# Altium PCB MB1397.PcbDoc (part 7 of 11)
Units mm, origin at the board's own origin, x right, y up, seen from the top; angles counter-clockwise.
Board outline 118.24 x 172.86 mm, 6 copper layers (Top Layer, L2_GND, L3_VCC, L4_SIG, L5_GND, Bottom Layer), stack 1.631 mm thick; 819 components, 632 nets, 2875 pads, 1523 vias.
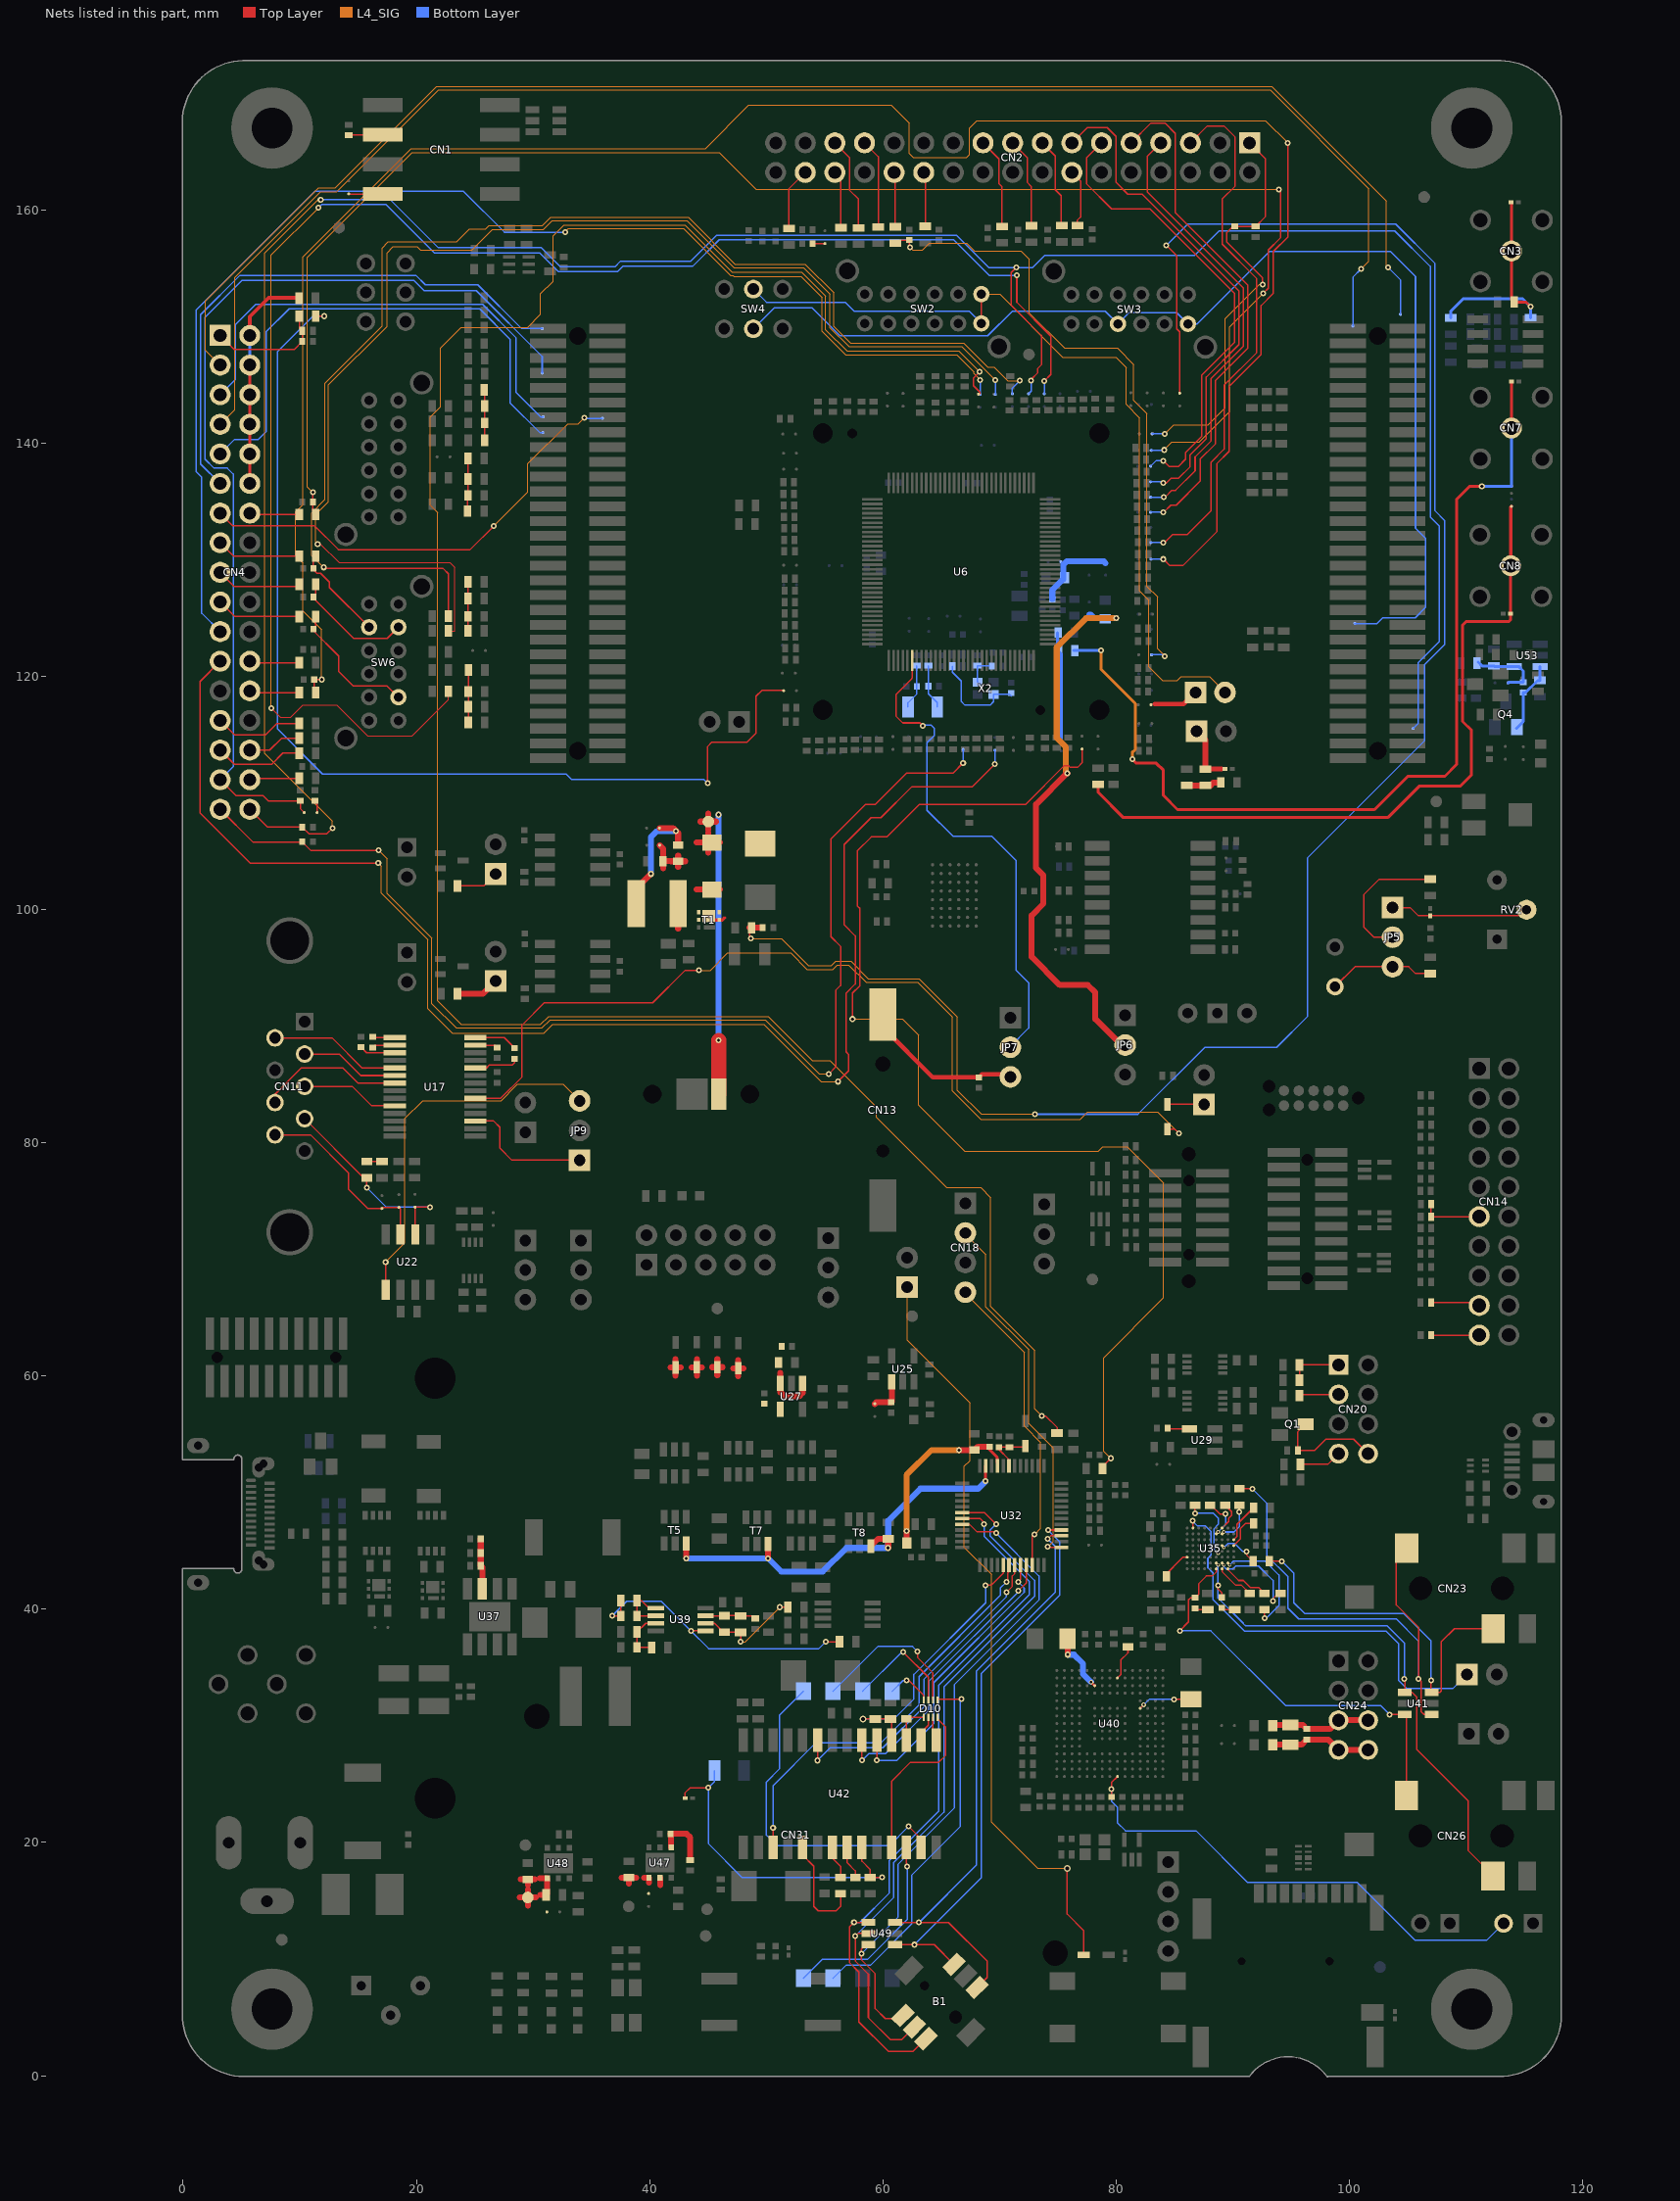
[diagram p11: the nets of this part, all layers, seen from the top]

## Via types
v1: diameter 0.508, hole 0.254, Top Layer to Bottom Layer, tented both sides, 1330 vias
v2: diameter 0.406, hole 0.203, Top Layer to Bottom Layer, tented both sides, 115 vias
v3: diameter 0.508, hole 0.254, Top Layer to Bottom Layer, 33 vias
v4: diameter 0.305, hole 0.152, Top Layer to Bottom Layer, tented both sides, 26 vias
v5: diameter 0.61, hole 0.305, Top Layer to Bottom Layer, tented both sides, 14 vias
v6: diameter 0.61, hole 0.33, Top Layer to Bottom Layer, tented both sides, 2 vias
v7: diameter 0.381, hole 0.203, Top Layer to Bottom Layer, tented both sides, 2 vias
v8: diameter 0.508, hole 0.203, Top Layer to Bottom Layer, tented both sides, 1 vias

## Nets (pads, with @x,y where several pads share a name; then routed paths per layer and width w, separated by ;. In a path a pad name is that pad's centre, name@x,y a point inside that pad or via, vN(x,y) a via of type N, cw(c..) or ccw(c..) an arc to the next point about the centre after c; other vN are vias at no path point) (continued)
MC1_PWM_1L: CN2.5 SB79.1 | length 46.5
  Top Layer w0.127: v1(84.046,131.47) 84.15,131.47 84.808,132.128 86.078,132.128 88.135,134.186 88.135,138.351 89.253,139.469 89.253,144.955 92.047,147.749 92.047,154.099 89.101,157.046 89.101,160.932 90.206,162.037 90.206,166.228 89.253,167.18 87.805,167.18 CN2.5@86.36,165.735
  Bottom Layer w0.127: SB79.1@82.967,131.47 v1(84.046,131.47)
MC1_PWM_2H: CN2.7 SB76.1 | length 38.5
  Top Layer w0.127: CN2.7@83.82,165.735 82.649,164.564 82.649,161.541 90.904,153.286 90.904,148.288 88.11,145.494 88.11,140.155 86.764,138.808 86.764,137.615 85.087,135.938 84.775,135.938 84.191,135.357 v1(84.074,135.357)
  Bottom Layer w0.127: SB76.1@82.95,135.357 SB76.1@82.95,135.357 v1(84.074,135.357)
MC1_PWM_2L: CN2.9 SB77.1 | length 44.3
  Top Layer w0.127: CN2.9@81.28,165.735 82.979,167.434 84.173,167.434 85.062,166.545 85.062,159.763 91.285,153.54 91.285,148.13 88.491,145.336 88.491,139.901 87.196,138.605 87.196,136.726 85.138,134.668 84.681,134.668 84.074,134.061 v1(84.021,134.061)
  Bottom Layer w0.127: SB77.1@82.949,134.061 v1(84.021,134.061)
MC1_PWM_3H: CN2.11 SB73.1 | length 40.3
  Top Layer w0.127: CN2.11@78.74,165.735 77.442,164.437 77.442,162.227 79.601,160.068 82.903,160.068 90.142,152.829 90.142,148.638 87.348,145.844 87.348,140.586 85.951,139.189 85.951,138.605 85.316,137.97 84.552,137.97 v1(84.046,138.478)
  Bottom Layer w0.127: SB73.1@82.949,138.016 83.414,138.478 v1(84.046,138.478)
MC1_PWM_3L: CN2.13 SB74.1 | length 43.8
  Top Layer w0.127: CN2.13@76.2,165.735 77.518,167.053 79.22,167.053 79.982,166.291 79.982,162.354 80.998,161.338 82.217,161.338 90.523,153.032 90.523,148.445 87.729,145.651 87.729,140.383 86.332,138.986 86.332,137.97 85.354,136.992 84.719,136.992 84.3,136.573 v1(84.046,136.573)
  Bottom Layer w0.127: SB74.1@82.945,136.679 83.942,136.677 v1(84.046,136.573)
MC1_STOP: C1.2 CN2.1 R9.1 SB69.1 | length 35.8
  Top Layer w0.127: CN2.1@91.44,165.735 92.809,164.363 92.809,159.428 R9.1@91.945,158.565 89.992,158.565 89.482,158.054 89.482,157.223 92.555,154.15 v1(92.555,153.591)
  L4_SIG w0.102: v1(84.173,140.787) 84.938,141.552 87.881,141.552 89.355,143.025 89.355,150.67 92.276,153.591 v1(92.555,153.591)
  Bottom Layer w0.127: SB69.1@83.078,140.788 v1(84.173,140.787)
MC1_Temp: C5.2 R7.2 SB100.1 | length 55.9
  Top Layer w0.127: R7.2@61.059,156.957 61.159,157.056 61.498,157.394 C5.2@62.27,157.395 62.271,156.817 v1(62.329,156.759)
  L4_SIG w0.102: v1(62.329,156.759) 62.55,156.538 63.396,156.538 63.98,157.122 67.183,157.122 67.843,156.461 71.854,156.461 72.565,155.75 72.565,151.127 75.562,148.13 80.109,148.13 81.506,146.733 81.506,143.634 82.624,142.517 82.624,127.709 83.538,126.794 83.538,122.347 v1(84.173,121.714)
  Bottom Layer w0.127: SB100.1@83.022,121.841 84.049,121.841 v1(84.173,121.714)
MC2_Ain: R103.2 SB60.1 | length 108.3
  Top Layer w0.102: v1(11.529,131.343) 11.76,131.343 13.36,129.743 22.875,129.743 23.298,129.32 23.298,123.879 R103.2@22.751,123.879
  L4_SIG w0.102: v1(11.529,131.343) 11.368,131.504 11.368,133.875 12.464,134.971 12.464,144.984 17.475,149.996 17.475,156.312 18.006,156.842 20.069,156.842 20.345,156.566 24.762,156.566 26.502,158.306 30.899,158.306 31.646,159.052 43.183,159.052 47.206,155.029 53.2,155.029 55.471,152.758 55.471,149.863 57.076,148.257 66.774,148.257 69.06,145.971 69.06,145.969 v1(69.642,145.39)
  Bottom Layer w0.127: SB60.1@69.642,144.178 v1(69.642,145.39)
MC2_Bin: R99.2 SB59.1 | length 109.5
  Top Layer w0.127: v1(12.037,129.334) 12.139,129.233 22.299,129.233 22.751,128.781 R99.2@22.751,125.166
  L4_SIG w0.102: v1(12.037,129.334) 11.021,130.35 11.021,134.01 12.162,135.151 12.162,145.115 17.069,150.022 17.069,156.721 17.596,157.249 23.442,157.249 24.559,158.366 25.931,158.366 26.223,158.659 30.82,158.659 31.519,159.357 43.31,159.357 47.323,155.344 53.317,155.344 55.776,152.885 55.776,149.99 57.203,148.562 66.901,148.562 68.958,146.505 69.543,146.505 70.711,145.336 v1(71.727,145.336)
  Bottom Layer w0.127: SB59.1@71.096,144.216 71.095,144.706 v1(71.727,145.336)
MC2_BusVoltage: C22.1 R77.2 SB72.1 | length 139.7
  Top Layer w0.127: v1(11.118,135.76) 11.118,134.107 R77.2@11.36,133.866 ; v1(92.606,152.829) 93.038,153.261 93.038,156.538 94.079,157.579 94.079,161.618 v1(93.952,161.745)
  L4_SIG w0.102: v1(11.118,135.76) 10.64,136.238 10.64,155.903 19.632,164.894 45.946,164.894 49.096,161.745 v1(93.952,161.745) ; v1(84.112,139.41) 84.78,140.078 87.119,140.078 89.71,142.669 89.71,149.934 v1(92.606,152.829)
  Bottom Layer w0.127: SB72.1@82.999,139.37 84.071,139.37 v1(84.112,139.41)
MC2_Cin: R119.2 SB57.1 | length 140
  Top Layer w0.102: v1(7.544,117.272) 8.331,116.484 9.205,116.484 10.271,117.551 13.162,117.551 15.829,114.884 19.634,114.884 22.751,118.001 R119.2@22.751,118.707
  Top Layer w0.127: v1(71.478,154.381) 71.478,152.062 74.394,149.146 74.394,145.872 v1(73.83,145.308)
  L4_SIG w0.102: v1(7.544,117.272) 7.544,156.108 v1(11.605,160.17)
  Bottom Layer w0.127: v1(11.605,160.17) 11.872,160.437 17.409,160.437 21.562,156.284 30.592,156.284 32.192,154.683 37.234,154.683 37.691,155.141 43.685,155.141 45.971,157.427 66.063,157.427 69.108,154.381 v1(71.478,154.381) ; SB57.1@73.831,144.216 v1(73.83,145.308)
MC2_CurrentA+: C23.2 R86.1 SW6.8 | length 8.4
  Top Layer w0.127: R86.1@11.36,130.302 11.135,130.076 11.135,129.159 11.466,128.826 11.783,128.826 12.545,128.064 12.545,127.607 SW6.8@15.951,124.202
MC2_CurrentB+: C24.2 R92.1 SW6.5 | length 10.4
  Top Layer w0.127: R92.1@11.36,127.889 11.359,126.97 11.135,126.746 11.135,126.721 14.615,123.238 17.488,123.238 SW6.5@18.451,124.202
MC2_CurrentC+: C26.2 R100.1 SW6.2 | length 11.8
  Top Layer w0.127: R100.1@11.36,125.103 11.359,124.27 11.15,124.063 11.09,124.003 11.09,123.977 13.332,121.735 13.332,120.419 14.577,119.174 17.478,119.174 SW6.2@18.451,118.202
MC2_DissipativeBrake: CN4.23 SB112.1 | length 121.9
  Top Layer w0.127: CN4.23@3.175,121.285 1.445,119.555 1.445,108.278 5.738,103.985 v1(16.736,103.985) ; v1(56.131,85.24) 57.059,86.167 57.059,87.579 56.843,87.795 56.843,92.829 57.63,93.616 57.63,97.737 56.67,98.697 56.67,105.559 58.982,107.871 59.817,107.871 62.484,110.538 67.673,110.538 v1(69.604,112.469)
  L4_SIG w0.102: v1(16.736,103.985) 16.99,103.731 16.99,101.42 20.978,97.432 20.978,91.488 23.061,89.405 30.935,89.405 31.671,90.142 49.807,90.142 54.709,85.24 v1(56.131,85.24)
  Bottom Layer w0.127: v1(69.604,112.469) SB112.1@69.604,113.657
MC2_EnA: C37.2 CN4.31 SB32.1 SB52.1 | length 84.9
  Top Layer w0.127: CN4.31@3.175,111.125 4.521,109.776 6.83,109.776 7.285,109.322 C37.2@10.044,109.323 10.043,108.651 SB32.1@10.385,108.312
  Bottom Layer w0.127: CN4.31@3.175,111.125 4.29,112.24 4.29,137.335 3.782,137.843 2.639,137.843 1.877,138.605 1.877,150.772 5.052,153.947 19.784,153.947 20.673,153.058 25.143,153.058 30.785,147.417 SB52.1@30.785,145.999
MC2_EnB: C42.2 CN4.33 SB108.1 | length 103.3
  Top Layer w0.127: CN4.33@3.175,108.585 5.969,105.791 10.218,105.791 10.93,105.077 v1(16.761,105.077) ; v1(55.344,85.9) 55.979,86.535 55.979,93.109 56.36,93.49 56.36,96.843 55.535,97.668 55.535,106.041 58.508,109.014 59.342,109.014 62.009,111.681 65.989,111.681 v1(66.878,112.57)
  L4_SIG w0.102: v1(16.761,105.077) 17.498,104.341 17.498,101.369 21.333,97.533 21.333,91.925 23.421,89.837 30.782,89.837 31.468,90.523 49.908,90.523 54.531,85.9 v1(55.344,85.9)
  Bottom Layer w0.127: v1(66.878,112.57) SB108.1@66.878,113.715
MC2_EnIndex: C39.2 CN4.34 SB58.1 SB106.1 | length 222.3
  Top Layer w0.127: CN4.34@5.715,108.585 7.239,107.058 C39.2@10.218,107.06 10.787,106.487 12.304,106.487 v1(12.799,106.982) ; v1(71.422,155.039) 70.99,154.607 70.99,151.813 73.581,149.222 73.581,146.708 73.276,146.403 73.276,146.022 72.707,145.453 v1(72.707,145.362)
  L4_SIG w0.102: v1(11.783,160.856) 11.58,160.856 7.008,156.284 7.008,113.373 12.799,107.582 v1(12.799,106.982)
  Bottom Layer w0.127: v1(11.783,160.856) 17.777,160.856 21.892,156.741 30.721,156.741 32.347,155.115 37.031,155.115 37.513,155.598 43.533,155.598 45.743,157.808 66.317,157.808 69.085,155.039 v1(71.422,155.039) 72.819,155.039 73.848,156.068 74.325,156.068 74.338,156.08 86.713,156.08 88.821,158.189 103.883,158.189 106.931,155.141 106.931,133.652 107.693,132.89 107.693,122.979 105.89,121.176 105.89,115.946 SB106.1@105.465,115.521 ; SB58.1@72.479,144.216 72.631,144.366 72.707,144.445 v1(72.707,145.362)
MC2_ICL_SHUTOUT: CN4.21 SB61.1 | length 109.8
  L4_SIG w0.102: v1(32.741,158.073) 33.043,158.375 42.89,158.375 46.911,154.353 47.14,154.353 47.216,154.277 52.982,154.277 54.785,152.474 54.785,149.578 56.792,147.571 66.317,147.571 67.79,146.098 67.79,145.946 v1(68.331,145.407)
  Bottom Layer w0.127: CN4.21@3.175,123.825 1.598,125.4 1.598,137.056 1.115,137.538 1.115,151.407 11.3,161.592 24.026,161.592 27.546,158.073 v1(32.741,158.073) ; SB61.1@68.329,144.175 68.331,144.175 v1(68.331,145.407)
MC2_PWM_1H: CN4.3 SB49.1 | length 129.1
  L4_SIG w0.102: CN4.3@3.175,146.685 1.928,147.93 1.928,152.194 11.605,161.872 13.028,161.872 21.74,170.584 93.317,170.584 103.172,160.729 103.172,155.191 v1(103.299,155.064)
  Bottom Layer w0.127: v1(103.299,155.064) 104.366,153.998 SB49.1@104.366,151.044
MC2_PWM_1L: CN4.5 SB64.1 | length 40.4
  Bottom Layer w0.127: CN4.5@3.175,144.145 4.493,145.463 4.493,150.162 6.22,151.889 25.677,151.889 28.547,149.019 28.547,144.32 30.63,142.24 SB64.1@30.871,142.24
MC2_PWM_2H: CN4.7 SB50.1 | length 132.9
  L4_SIG w0.102: CN4.7@3.175,141.605 4.417,142.847 4.417,154.175 11.796,161.554 13.167,161.554 21.892,170.279 93.19,170.279 101.671,161.798 101.671,155.595 v1(100.988,154.912)
  Bottom Layer w0.127: SB50.1@100.295,150.035 100.294,154.219 v1(100.988,154.912)
MC2_PWM_2L: CN4.9 SB68.1 | length 45.4
  Bottom Layer w0.127: CN4.9@3.175,139.065 4.417,140.307 6.449,140.307 7.109,140.967 7.109,149.527 9.091,151.508 25.423,151.508 28.039,148.892 28.039,143.431 30.579,140.891 SB68.1@30.843,140.891
MC2_PWM_3H: CN4.11 SB51.1 | length 47.8
  Bottom Layer w0.127: CN4.11@3.175,136.525 1.496,138.201 1.496,151 4.874,154.379 19.962,154.379 20.775,153.566 25.27,153.566 29.027,149.809 SB51.1@30.785,149.811
MC2_PWM_3L: CN4.13 SB66.1 | length 40.2
  Top Layer w0.127: CN4.13@3.175,133.985 4.267,132.89 11.275,132.89 13.307,130.858 24.61,130.858 v1(26.642,132.89)
  L4_SIG w0.102: v1(26.642,132.89) 29.563,135.811 29.563,138.224 32.992,141.653 33.881,141.653 v1(34.389,142.161)
  Bottom Layer w0.127: v1(34.389,142.161) 34.437,142.113 SB66.1@35.948,142.113
MC2_STOP: R21.1 SB23.1 | length 90.7
  Top Layer w0.127: R21.1@11.36,150.876 v1(12.113,150.876) ; v1(44.968,110.818) 44.968,113.98 45.339,114.351 48.362,114.351 49.121,115.11 49.121,118.285 49.629,118.793 SB23.1@51.415,118.793
  Bottom Layer w0.127: v1(12.113,150.876) 11.123,150.876 8.1,147.853 8.1,115.466 11.948,111.618 32.84,111.618 33.31,111.148 44.638,111.148 v1(44.968,110.818)
MC2_Temp: C31.2 R120.2 SB83.1 | length 178.8
  Top Layer w0.127: R120.2@11.36,118.603 11.234,118.727 C31.2@11.235,119.717 v1(11.869,119.715) ; v1(84.046,130.045) 84.602,129.487 85.722,129.487 88.618,132.382 88.618,138.224 89.685,139.291 89.685,144.849 92.428,147.592 92.428,151.788 93.469,152.829 93.469,156.411 94.714,157.655 v1(94.714,165.732)
  L4_SIG w0.102: v1(11.869,119.715) 11.869,123.99 10.259,125.6 10.259,129.715 9.624,130.35 9.624,134.08 10.259,134.715 10.259,155.953 19.548,165.242 44.773,165.242 48.486,168.958 60.703,168.958 62.253,167.409 62.253,164.818 62.608,164.462 67.155,164.462 67.434,164.742 67.434,167.002 68.069,167.637 92.809,167.637 v1(94.714,165.732)
  Bottom Layer w0.127: SB83.1@82.979,130.046 v1(84.046,130.045)
MC_DAC_OUT1: SB93.1 SW3.3 SW3.6 SW4.2 | length 99.5
  Bottom Layer w0.127: SW4.2@48.889,149.792 SW4.2@48.889,149.792 50.709,151.61 53.896,151.61 56.309,149.197 68.984,149.197 71.092,151.305 79.063,151.305 SW3.3@80.146,150.222 SW3.3@80.146,150.222 81.105,151.178 85.189,151.178 SW3.6@86.146,150.222 86.949,150.221 93.139,156.411 103.528,156.411 105.661,154.277 105.661,132.687 106.525,131.823 106.525,125.905 105.636,125.016 102.842,125.016 102.337,124.511 100.421,124.511 SB93.1@100.421,124.508
MC_DAC_OUT2: CN32.1 SB24.1 | length 3.9
  Top Layer w0.381: 83.307,117.602 85.781,117.602 CN32.1@86.792,118.613
MFX_aGPIO1: R241.1 T5.3 T7.3 T8.3 U32.11 | length 37
  Top Layer w0.254: v1(68.806,50.975) U32.11@68.807,52.292
  Top Layer w0.508: v1(43.134,44.371) T5.3@43.134,45.613 ; v1(50.15,44.359) T7.3@50.15,45.585 ; T8.3@58.951,45.409 59.578,46.035 R241.1@60.456,46.037 60.455,45.291 v1(60.424,45.26)
  Bottom Layer w0.508: v1(43.134,44.371) 43.147,44.359 v1(50.15,44.359) 51.28,43.228 54.836,43.228 56.868,45.26 v1(60.424,45.26) 60.455,45.291 60.455,47.577 63.218,50.34 68.171,50.34 v1(68.806,50.975)
MFX_IRQ_OUT: R232.1 SB26.1 | length 101.9
  Top Layer w0.127: v1(57.389,90.612) 57.389,92.836 58.011,93.459 58.011,100.097 57.81,100.298 57.81,105.031 59,106.22 60.328,106.22 63.122,109.014 72.235,109.014 75.557,112.337 75.903,112.337 76.05,112.189 76.68,112.189 77.064,112.573 SB26.1@77.064,113.759 ; R232.1@78.829,52.063 78.829,52.235 v1(79.538,52.944)
  L4_SIG w0.102: v1(57.389,90.612) 57.401,90.599 61.665,90.599 63.053,89.211 63.053,83.221 67.003,79.271 78.456,79.271 78.842,79.657 80.942,79.657 84.071,76.528 84.071,66.698 78.941,61.567 78.941,53.541 v1(79.538,52.944)
MFX_JOY_DOWN: B1.3 U32.19 U49.4 | length 62
  Top Layer w0.127: U49.4@58.749,13.142 v1(57.516,13.142) 57.122,12.748 57.122,9.7 57.935,8.887 57.935,4.616 60.471,2.08 62.581,2.08 B1.3@63.687,3.188 B1.3@63.688,3.188 ; U32.19@66.807,47.792 68.308,47.79 68.679,47.419 v1(68.679,47.292)
  Bottom Layer w0.127: v1(57.516,13.142) 58.024,13.142 60.551,15.669 60.551,18.463 64.771,22.683 64.771,33.478 72.553,41.26 72.553,42.372 68.679,46.246 v1(68.679,47.292)
MFX_JOY_LEFT: B1.1 U32.20 U49.6 | length 56.3
  Top Layer w0.127: U49.6@58.749,11.242 58.534,11.242 58.163,10.869 v1(58.163,10.462) 58.163,9.929 59.337,8.755 59.337,5.763 60.198,4.902 61.441,4.902 B1.1@61.707,5.168 ; U32.20@66.807,47.292 66.807,47.292 67.412,47.292 68.044,46.657 69.568,46.657 v1(69.695,46.53)
  Bottom Layer w0.127: v1(58.163,10.462) 61.313,13.612 61.313,18.148 66.142,22.977 66.142,33.553 73.378,40.79 73.378,42.847 v1(69.695,46.53)
MFX_JOY_RIGHT: B1.6 U32.39 U49.3 | length 51.1
  Top Layer w0.127: U49.3@61.049,13.142 v1(63.091,13.142) 65.618,13.142 68.933,9.827 68.933,8.433 B1.6@68.071,7.572 B1.6@68.071,7.572 B1.6@68.072,7.572 ; v1(74.14,46.022) 74.409,46.292 U32.39@75.307,46.292
  Bottom Layer w0.127: v1(63.091,13.142) 68.021,18.072 68.021,34.696 74.775,41.45 74.775,45.387 v1(74.14,46.022)
MFX_JOY_SEL: B1.2 U32.18 U49.5 | length 60.6
  Top Layer w0.127: U49.5@58.749,12.192 57.836,12.192 v1(57.63,11.986) 57.63,9.827 58.753,8.705 58.753,4.976 60.632,3.096 61.615,3.096 B1.2@62.697,4.178 ; U32.18@66.807,48.292 68.697,48.29 v1(69.695,47.292)
  Bottom Layer w0.127: v1(57.63,11.986) 60.932,15.288 60.932,18.306 65.227,22.601 65.227,33.325 72.997,41.095 72.997,42.466 69.187,46.276 69.187,46.784 v1(69.695,47.292)
MFX_JOY_UP: B1.4 U32.40 U49.1 | length 48
  Top Layer w0.127: U49.1@61.049,11.242 v1(62.71,11.242) 64.402,11.242 B1.4@66.09,9.551 ; B1.4@66.091,9.552 B1.4@66.091,9.553 ; v1(74.148,46.792) U32.40@75.307,46.792
  Bottom Layer w0.127: v1(62.71,11.242) 68.441,16.973 68.441,34.481 75.156,41.196 75.156,45.781 v1(74.148,46.792)
MFX_SmartCard_1V8: R275.1 R276.2 U32.29 U42.18 | length 24.2
  Top Layer w0.127: v5(58.288,30.587) R275.1@59.336,30.587 R276.2@60.657,30.587 ; R276.2@60.657,30.587 60.744,30.5 60.744,28.763 U42.18@60.743,28.765 ; v1(68.806,42.06) 68.831,42.085 69.314,42.085 70.307,43.078 U32.29@70.307,43.79
  Bottom Layer w0.127: v5(58.288,30.587) 60.94,30.587 62.649,32.296 62.649,34.404 68.806,40.561 v1(68.806,42.06)
MFX_SmartCard_3/5V: U32.30 U42.3 | length 35.9
  Top Layer w0.127: U42.3@50.583,19.585 50.584,19.583 v1(50.584,21.257) ; v1(70.584,42.339) 70.711,42.466 70.711,43.101 70.805,43.195 U32.30@70.805,43.79
  Bottom Layer w0.127: v1(50.584,21.257) 50.584,24.879 54.266,28.562 59.854,28.562 63.094,31.801 63.094,34.214 70.076,41.196 70.076,41.831 v1(70.584,42.339)
MFX_SmartCard_CMDVCC: U32.32 U42.19 | length 25
  Top Layer w0.127: v1(59.474,27.038) U42.19@59.474,28.763 ; v1(71.6,42.339) 71.806,42.545 U32.32@71.806,43.79
  Bottom Layer w0.127: v1(59.474,27.038) 61.192,27.038 64.364,30.21 64.364,33.706 72.108,41.45 72.108,41.831 v1(71.6,42.339)
MFX_SmartCard_OFF: U32.31 U42.23 | length 28.1
  Top Layer w0.127: U42.23@54.393,28.765 54.394,28.763 v1(54.394,27.033) ; v1(70.584,41.45) 71.092,41.958 71.092,42.847 71.305,43.061 U32.31@71.305,43.79
  Bottom Layer w0.127: v1(54.394,27.033) 55.476,28.118 59.997,28.118 63.536,31.656 63.536,34.021 70.584,41.069 v1(70.584,41.45)
MFX_SmartCard_RST: U32.33 U42.20 | length 25.2
  Top Layer w0.127: U42.20@58.203,28.765 58.204,28.763 v1(58.204,27.038) ; v1(71.6,41.577) 72.306,42.283 U32.33@72.306,43.79
  Bottom Layer w0.127: v1(58.204,27.038) 58.776,27.61 60.201,27.61 63.929,31.339 63.929,33.81 71.6,41.481 v1(71.6,41.577)
MFX_SWCLK: CN18.2 U32.37 | length 31.3
  Top Layer w0.127: v1(74.14,45.362) 74.211,45.291 U32.37@75.307,45.292
  L4_SIG w0.102: CN18.2@67.028,72.184 68.806,70.406 68.806,65.936 72.489,62.253 72.489,55.928 74.597,53.82 74.597,45.819 v1(74.14,45.362)
MFX_SWDIO: CN18.4 U32.34 | length 26.3
  Top Layer w0.127: U32.34@72.807,43.79 72.807,46.276 72.934,46.403 v1(72.997,46.403)
  L4_SIG w0.102: CN18.4@67.028,67.104 72.108,62.024 72.108,55.7 73.53,54.277 73.53,46.937 v1(72.997,46.403)
MFX_WAKEUP: R223.2 SB6.1 | length 198
  Top Layer w0.127: v1(68.298,146.098) 67.765,145.565 67.765,144.904 68.311,144.358 SB6.1@68.311,144.191 ; v1(73.632,56.563) 73.965,56.563 74.927,55.601 74.927,55.108 R223.2@74.929,55.109
  L4_SIG w0.102: v1(68.298,146.098) 66.518,147.876 56.919,147.876 55.09,149.705 55.09,152.601 53.033,154.658 47.038,154.658 43.019,158.677 32.634,158.677 31.709,157.752 31.709,153.845 30.655,152.791 30.655,151.026 29.538,149.908 23.848,149.908 22.07,148.13 22.07,143.101 21.181,142.212 21.181,134.668 21.816,134.033 21.816,92.179 23.853,90.142 30.655,90.142 31.341,90.828 50.162,90.828 53.947,87.043 55.446,87.043 59.433,83.055 59.433,82.184 65.471,76.147 68.374,76.147 69.238,75.283 69.238,65.961 72.997,62.202 72.997,57.198 v1(73.632,56.563)
NetC12_2: C12.2 SB2.2 | length 1.1
  Top Layer w0.127: C12.2@53.977,157.087 55.016,157.086 SB2.2@55.027,157.098
NetC16_2: C16.2 CN4.1 R21.2 R23.1 | length 10.1
  Top Layer w0.127: CN4.1@3.175,149.225 4.394,148.003 9.512,148.003 C16.2@10.218,148.709 R23.1@10.218,149.603 ; R21.2@9.96,150.876 9.959,149.863 R23.1@10.218,149.603 ; R23.1@10.218,149.606 R23.1@10.218,149.603
NetC18_1: C18.1 R31.1 R51.1 R59.2 | length 4.3
  Top Layer w0.127: R31.1@25.821,144.542 25.845,144.516 R59.2@25.846,140.228
NetC21_1: C21.1 R61.1 R66.1 R76.2 | length 4.5
  Top Layer w0.127: C21.1@24.389,135.509 24.389,134.182 R76.2@24.395,134.176 ; C21.1@24.413,135.509 R66.1@24.413,136.925 R61.1@24.413,138.674
NetC25_1: C25.1 R91.1 R95.1 R104.2 | length 4.2
  Top Layer w0.127: R104.2@24.417,123.873 24.42,123.876 R91.1@24.421,128.079
NetC32_1: C32.1 R115.2 R122.1 R125.1 | length 4.5
  Top Layer w0.127: R125.1@24.447,116.027 R115.2@24.447,120.543
NetC36_1: C36.1 R153.1 R154.1 | length 3
  Top Layer w0.127: R153.1@86.034,110.642 86.035,110.642 R153.1@86.035,110.64 ; R154.1@87.647,110.642 87.648,110.642 R154.1@87.648,110.64
  Top Layer w0.508: R153.1@86.034,110.642 86.035,110.64 R154.1@87.647,110.642 87.648,110.64 88.085,110.64 88.339,110.894 C36.1@88.962,110.894
NetC38_2: C38.2 SB32.2 | length 1.1
  Top Layer w0.127: C38.2@11.294,109.323 11.483,109.131 SB32.2@11.485,108.312
NetC41_1: C41.1 C43.2 C45.2 D1.2 LD5.1 SB34.1 TP3.1 | length 35.3
  Top Layer w0.254: LD5.1@45.916,84.149 LD5.1@45.916,84.161
  Top Layer w0.508: SB34.1@40.85,105.518 40.851,105.517 41.14,105.225 C45.2@41.142,104.151 ; 41.14,103.525 C45.2@41.142,104.151 ; 41.641,104.15 C45.2@41.142,104.151 ; 41.816,104.135 C43.2@42.44,104.135 ; 42.438,103.635 C43.2@42.44,104.135 ; 42.438,104.633 C43.2@42.44,104.135 ; 43.063,104.135 C43.2@42.44,104.135 ; 44.028,105.74 D1.2@45.027,105.74 ; 44.348,107.536 TP3.1@45.028,107.536 ; 45.027,104.861 D1.2@45.027,105.74 ; 45.027,106.619 D1.2@45.027,105.74 ; 45.027,106.858 TP3.1@45.028,107.536 ; 45.027,108.214 TP3.1@45.028,107.536 ; 45.707,107.536 TP3.1@45.028,107.536 ; v1(45.916,88.798) v1@45.926,88.788 ; D1.2@46.027,105.74 D1.2@45.027,105.74
  Top Layer w1.27: LD5.1@45.926,84.161 v1@45.926,88.788
  Bottom Layer w0.508: v1(45.916,88.798) v1(45.916,108.125)
NetC43_1: C43.1 L2.2 SB33.1 | length 11.3
  Top Layer w0.508: L2.2@38.839,100.554 38.839,101.78 v1(40.104,103.045) ; SB33.1@40.858,106.982 42.009,106.982 v1(42.263,106.728) 42.438,106.553 C43.1@42.44,105.535
  Bottom Layer w0.508: v1(40.104,103.045) 40.104,106.195 40.637,106.728 v1(42.263,106.728)
NetC49_2: C49.2 R172.2 SB10.2 | length 171.4
  Top Layer w0.127: R172.2@48.567,98.445 48.567,97.605 v1(48.664,97.508) ; v1(84.3,156.944) 85.189,156.055 85.189,149.781 85.443,149.527 SB10.2@85.443,144.272
  Top Layer w0.508: R172.2@48.567,98.445 C49.2@49.451,98.445
  L4_SIG w0.102: v1(48.664,97.508) 51.28,97.508 53.617,95.171 55.598,95.171 55.979,95.552 57.249,95.552 58.748,94.054 63.116,94.054 66.396,90.775 66.396,84.501 68.45,82.446 v1(73.02,82.446)
  Bottom Layer w0.127: v1(73.02,82.446) 81.862,82.446 87.602,88.186 93.749,88.186 96.416,90.853 96.416,104.442 106.423,114.45 106.423,120.978 108.151,122.705 108.151,133.373 107.338,134.186 107.338,155.395 103.96,158.773 86.129,158.773 v1(84.3,156.944)
NetC54_2: C54.2 U17.3 | length 3.1
  Top Layer w0.127: C54.2@15.24,88.195 15.723,87.711 U17.3@18.14,87.713
NetC55_1: C55.1 U17.1 | length 1.9
  Top Layer w0.127: C55.1@16.256,89.07 16.312,89.012 U17.1@18.14,89.013
NetC55_2: C55.2 U17.2 | length 2
  Top Layer w0.127: C55.2@16.256,88.17 16.449,88.362 U17.2@18.14,88.363
NetC56_2: C56.2 U17.27 | length 2
  Top Layer w0.127: U17.27@25.04,88.363 26.723,88.362 C56.2@26.924,88.163
NetC57_1: C57.1 U17.24 | length 3.9
  Top Layer w0.127: U17.24@25.04,86.413 26.01,86.411 26.261,86.662 28.219,86.662 28.42,86.863 C57.1@28.42,87.229
NetC57_2: C57.2 U17.28 | length 3.7
  Top Layer w0.127: U17.28@25.04,89.013 27.536,89.012 C57.2@28.42,88.128
NetC59_2: C59.2 CN13.1 JP7.3 | length 14.1
  Top Layer w0.381: CN13.1@59.992,91.004 59.992,89.888 64.282,85.598 C59.2@68.227,85.598 68.481,85.852 70.708,85.852 JP7.3@70.924,85.647 JP7.3@70.924,85.725
NetC60_1: C60.1 CN11.4 SB37.1 U22.6 | length 18
  Top Layer w0.127: CN11.4@10.414,82.063 15.486,76.987 C60.1@15.748,76.989 v1(15.748,76.149) ; U22.6@19.905,72.14 19.881,72.166 SB37.1@19.88,74.477 v1(21.176,74.475) ; U22.6@19.906,72.139 U22.6@19.907,72.141
  Bottom Layer w0.127: v1(15.748,76.149) 17.419,74.475 v1(21.176,74.475)
NetC60_2: C60.2 R192.1 | length 1.3
  Top Layer w0.127: C60.2@15.748,78.389 C60.2@15.748,78.389 R192.1@17.044,78.387
NetC63_2: C63.2 C66.1 D3.2 D4.2 D5.2 D6.2 U27.1 U27.3 | length 13.9
  Top Layer w0.508: 41.77,60.736 D5.2@42.219,60.738 ; 42.217,60.028 D5.2@42.219,60.738 ; 42.217,61.445 D5.2@42.219,60.738 ; 42.667,60.736 D5.2@42.219,60.738 ; 43.591,60.744 D4.2@44.041,60.745 ; 44.041,60.035 D4.2@44.041,60.745 ; 44.041,61.453 D4.2@44.041,60.745 ; 44.488,60.744 D4.2@44.041,60.745 ; 45.352,60.754 D3.2@45.799,60.754 ; 45.799,60.046 D3.2@45.799,60.754 ; 45.799,61.46 D3.2@45.799,60.754 ; 46.248,60.754 D3.2@45.799,60.754 ; 47.145,60.668 D6.2@47.594,60.67 ; 47.595,59.962 D6.2@47.594,60.67 ; 47.595,61.377 D6.2@47.594,60.67 ; 48.042,60.668 D6.2@47.594,60.67 ; 51.204,60.287 U27.3@51.204,59.352 51.204,58.604 51.556,58.252 52.802,58.252 53.104,58.554 U27.1@53.104,59.352
NetC71_2: C71.2 U27.4
NetC72_2: C72.2 SB41.1 U25.1 | length 3.2
  Top Layer w0.508: SB41.1@59.306,57.607 59.447,57.747 C72.2@60.706,57.747 60.753,57.794 U25.1@60.753,59.506
NetC74_2: C74.2 U29.4 | length 1.9
  Top Layer w0.127: C74.2@84.404,55.527 84.473,55.458 U29.4@86.264,55.459
NetC76_2: C76.2 C77.2 L3.2 U32.9 | length 15.5
  Top Layer w0.254: C77.2@69.145,53.945 69.144,53.685 69.807,53.023 U32.9@69.807,52.596
  Top Layer w0.508: L3.2@62.017,45.715 v1(62.017,46.716) ; v1(66.52,53.652) C76.2@67.861,53.653 68.153,53.945 C77.2@69.145,53.945
  L4_SIG w0.508: v1(62.017,46.716) 62.017,51.501 64.168,53.652 v1(66.52,53.652)
NetC78_2: C78.2 D7.1 R225.1 U32.7 | length 4.3
  Top Layer w0.127: U32.7@70.807,52.292 70.805,52.837 69.944,53.698 C78.2@69.945,53.903 72.111,53.901 D7.1@72.207,53.997
NetC85_1: C85.1 U35.E6 | length 6.4
  Top Layer w0.127: v1(86.761,48.23) C85.1@86.763,48.926 ; U35.E6@88.577,44.966 88.577,44.966 v4(88.735,44.806)
  Bottom Layer w0.127: v1(86.761,48.23) 88.341,48.23 88.745,47.826 88.745,47.267 88.364,46.886 88.364,45.176 v4(88.735,44.806)
NetC86_2: C86.2 U35.A7 | length 2.5
  Top Layer w0.127: U35.A7@89.077,46.966 89.634,47.523 89.634,47.8 89.888,48.054 89.888,48.374 89.339,48.925 C86.2@89.339,48.926
NetC87_1: C87.1 U35.B7 | length 3.6
  Top Layer w0.127: U35.B7@89.077,46.466 v4(89.235,46.624) ; v1(90.551,48.336) C87.1@90.552,48.926
  Bottom Layer w0.127: v4(89.235,46.624) 90.109,46.624 90.551,47.066 v1(90.551,48.336)
NetC87_2: C87.2 CN23.6 U41.4 | length 44.5
  Top Layer w0.127: C87.2@90.552,50.326 v1(91.676,50.325) ; CN23.6@104.91,45.233 104.013,44.336 104.013,40.361 105.918,38.456 v1(105.918,34.036) 106.147,33.807 106.147,31.217 106.388,30.975 U41.4@107.04,30.975
  Bottom Layer w0.127: v1(91.676,50.325) 92.936,49.065 92.936,44.574 94.714,42.796 94.714,40.095 95.645,39.164 104.022,39.164 105.918,37.269 v1(105.918,34.036)
NetC88_2: C88.2 U35.B6 | length 3.7
  Top Layer w0.127: C88.2@88.04,48.901 88.153,48.9 88.897,48.156 89.355,48.156 v1(89.38,48.181) ; U35.B6@88.577,46.466 88.577,46.464 v4(88.735,46.624)
  Bottom Layer w0.127: v4(88.735,46.624) 89.38,47.269 v1(89.38,48.181)
NetC90_2: C90.2 U35.C9 | length 3.5
  Top Layer w0.127: U35.C9@90.077,45.966 90.362,46.25 90.362,47.084 90.352,47.093 90.352,47.266 C90.2@91.787,48.701
NetC91_2: C91.2 U35.D9 | length 3
  Top Layer w0.127: U35.D9@90.077,45.466 90.65,46.038 90.65,46.911 91.11,47.371 C91.2@91.787,47.373
NetC95_1: C95.1 R247.1 R251.2 U37.3 | length 4.4
  Top Layer w0.508: C95.1@25.514,46.038 R247.1@25.514,44.815 R251.2@25.514,43.728 25.654,43.588 U37.3@25.654,41.745
NetC99_1: C99.1 U35.D7 | length 3.7
  Top Layer w0.127: U35.D7@89.077,45.466 v4(89.235,45.306) ; v1(91.183,44.955) 91.183,44.661 C99.1@91.727,44.117
  Bottom Layer w0.127: v4(89.235,45.306) 89.573,45.641 90.167,45.641 90.853,44.955 v1(91.183,44.955)
NetC99_2: C99.2 CN23.4 U41.6 | length 32.9
  Top Layer w0.127: C99.2@93.127,44.117 C99.2@93.133,44.117 v1(94.206,44.117) ; v1(106.991,33.902) 106.991,33.066 106.799,32.875 U41.6@107.04,32.875 107.757,32.875 107.874,32.992 107.874,37.211 108.994,38.331 CN23.4@112.31,38.333
  Bottom Layer w0.127: v1(94.206,44.117) 95.222,43.101 95.222,40.564 96.162,39.624 104.678,39.624 106.991,37.312 v1(106.991,33.902)
NetC101_2: C101.2 U35.F1 | length 2.6
  Top Layer w0.127: C101.2@84.297,42.822 84.468,42.994 84.468,43.209 85.315,44.055 85.725,44.465 U35.F1@86.077,44.466
NetC103_1: C103.1 U35.G8 | length 10.1
  Top Layer w0.127: U35.G8@89.577,43.966 v4(89.736,43.805) ; C103.1@92.71,39.965 92.71,39.263 v1(92.746,39.228)
  Bottom Layer w0.127: v4(89.736,43.805) 90.048,44.117 92.774,44.117 93.952,42.939 93.952,40.307 92.873,39.228 v1(92.746,39.228)
NetC103_2: C103.2 U35.H8 | length 4
  Top Layer w0.127: U35.H8@89.577,43.466 89.576,43.388 90.498,42.466 90.904,42.466 91.495,41.876 92.2,41.876 C103.2@92.71,41.365
NetC104_2: C104.2 U35.G7 | length 8.1
  Top Layer w0.127: U35.G7@89.077,43.966 v4(89.235,43.805) ; v1(93.444,40.688) 93.444,40.917 93.893,41.365 C104.2@94.107,41.365
  Bottom Layer w0.127: v4(89.235,43.805) 89.235,43.652 89.431,43.457 89.99,43.457 90.244,43.711 92.199,43.711 93.444,42.466 v1(93.444,40.688)
NetC105_2: C105.2 U35.H7 | length 3.4
  Top Layer w0.127: U35.H7@89.077,43.466 89.078,43.464 89.078,43.226 90.218,42.085 90.719,42.085 C105.2@91.448,41.356
NetC106_1: C106.1 CN26.4 U35.G6 U41.1 | length 45.3
  Top Layer w0.127: U35.G6@88.577,43.966 88.577,43.965 v4(88.735,43.805) ; v1(88.735,42.06) 88.735,41.73 89.047,41.417 C106.1@89.047,41.015 C106.1@89.047,41.006 ; v1(104.699,34.011) 104.74,33.969 U41.1@104.74,32.875 105.368,32.875 105.756,32.487 105.756,28 110.16,23.597 110.16,19.329 112.291,17.199 CN26.4@112.291,17.124
  Bottom Layer w0.127: v4(88.735,43.805) v1(88.735,42.06) 88.735,40.952 90.895,38.792 ; 90.885,38.782 91.085,38.583 103.223,38.583 104.699,37.107 v1(104.699,34.011)
NetC106_2: C106.2 R255.2 | length 1.2
  Top Layer w0.127: C106.2@89.047,40.104 89.197,39.954 R255.2@90.152,39.956
NetC107_1: C107.1 CN26.6 U35.H6 U41.3 | length 36.4
  Top Layer w0.127: v1(85.443,38.148) 86.205,38.91 86.205,40.815 86.375,40.985 86.761,40.985 86.763,40.987 87.094,41.316 87.094,42.212 87.729,42.847 88.242,42.847 88.577,43.182 U35.H6@88.577,43.466 ; v1(103.454,30.963) 103.467,30.975 U41.3@104.74,30.975 104.889,30.826 CN26.6@104.891,24.024
  Bottom Layer w0.127: v1(85.443,38.148) 88.11,38.148 94.508,31.75 102.667,31.75 v1(103.454,30.963)
NetC107_2: C107.2 R256.2 | length 1.1
  Top Layer w0.127: C107.2@86.761,40.084 86.891,39.954 R256.2@87.84,39.956
NetC110_1: C110.1 R260.1 R270.2 U39.5 | length 25.3
  Top Layer w0.127: v1(36.774,39.424) C110.1@37.519,39.425 R260.1@37.519,40.741 ; v1(43.533,38.148) 44.77,38.148 U39.5@44.78,38.14 ; v1(55.09,37.208) 56.276,37.208 R270.2@56.277,37.208
  Bottom Layer w0.127: v1(36.774,39.424) 38.033,40.683 40.998,40.683 v1(43.533,38.148) 45.057,36.624 54.506,36.624 v1(55.09,37.208)
NetC110_2: C110.2 R260.2 U39.1 U39.2 | length 4.8
  Top Layer w0.127: U39.2@40.53,39.441 40.516,39.425 C110.2@38.919,39.425 R260.2@38.919,40.741 39.29,40.741 39.941,40.089 U39.1@40.531,40.089
NetC111_1: C111.1 R262.2 R265.1 U39.6 | length 9.4
  Top Layer w0.127: U39.6@44.78,38.79 45.56,38.788 46.307,38.042 47.77,38.042 R265.1@47.802,38.012 v1(47.8,37.208) ; v1(51.153,40.178) R262.2@51.839,40.179
  L4_SIG w0.102: v1(47.8,37.208) 48.186,37.208 v1(51.153,40.178)
NetC111_2: C111.2 R265.2 R266.1 U39.7 | length 4.4
  Top Layer w0.127: U39.7@44.78,39.441 46.401,39.439 46.403,39.444 47.77,39.444 R265.2@47.802,39.412 48.854,39.411 R266.1@49.054,39.214
NetC114_2: C114.2 U40.J14 | length 3
  Top Layer w0.127: U40.J14@80.105,34.103 80.409,34.404 80.409,35.654 81.011,36.256 C114.2@81.011,36.772
NetC115_2: C115.2 U40.F13 | length 5.7
  Top Layer w0.254: v2(77.851,33.755) 78.034,33.572 ; v2(77.851,33.755) 78.034,33.572 ; U40.F13@78.155,33.453 78.034,33.572 ; U40.F13@78.155,33.453 78.034,33.572
  Top Layer w0.508: v1(75.832,36.106) C115.2@75.833,37.472
  Bottom Layer w0.508: v1(75.832,36.106) 76.385,36.106 77.163,35.329 77.163,34.442 v2@77.851,33.757
NetC120_2: C120.2 R268.1 R271.2 U39.3 | length 4.5
  Top Layer w0.127: R271.2@40.169,36.722 R271.2@40.169,36.722 C120.2@38.919,36.723 R268.1@38.919,38.051 39.658,38.79 U39.3@40.53,38.79
NetC122_2: C122.2 U40.M10 | length 4.7
  Top Layer w0.127: U40.M10@82.055,31.504 v2(82.357,31.806) ; v1(84.968,32.273) C122.2@86.402,32.275
  Bottom Layer w0.127: v2@82.359,31.806 82.827,32.273 v1(84.968,32.273)
NetC126_1: C126.1 D10.1 U42.17 | length 3.4
  Top Layer w0.127: U42.17@62.013,28.765 62.014,28.763 C126.1@62.014,30.587 ; C126.1@62.013,30.588 C126.1@62.014,30.587 ; D10.1@63.494,30.733 62.159,30.731 C126.1@62.014,30.587
NetC129_1: C129.1 C132.2 CN24.5 CN24.6 L6.2 | length 8.6
  Top Layer w0.508: L6.2@93.434,30.023 93.495,30.084 95.992,30.084 C132.2@96.342,29.736 ; C132.2@96.342,29.736 98.316,29.736 CN24.5@99.06,30.48 CN24.6@101.6,30.48
NetC129_2: C129.2 C132.1 CN24.7 CN24.8 L7.2 | length 8.7
  Top Layer w0.508: L7.2@93.434,28.385 95.89,28.385 C132.1@96.342,28.836 ; C132.1@96.342,28.836 98.164,28.836 CN24.7@99.06,27.94 CN24.8@101.6,27.94
NetC141_2: C141.2 CN30.2 U40.J1 | length 42.9
  Top Layer w0.127: C141.2@79.591,23.899 v1(79.591,24.559) 79.591,25.138 U40.J1@80.105,25.653
  Bottom Layer w0.127: v1(79.591,24.559) 79.591,23.556 80.094,23.05 80.094,21.704 80.795,21.003 86.84,21.003 91.285,16.558 100.683,16.558 105.636,11.605 111.755,11.605 CN30.2@113.215,13.066
NetC146_1: C146.1 R289.1 U47.1 | length 5
  Top Layer w0.508: U47.1@41.842,19.577 41.841,20.673 C146.1@41.773,20.742 43.16,20.742 43.472,20.429 R289.1@43.472,18.502
NetC149_2: C149.2 SB47.1 U47.4 U47.5 | length 3.2
  Top Layer w0.508: 37.589,16.993 C149.2@38.215,16.994 ; 38.214,16.495 C149.2@38.215,16.994 ; 38.837,16.993 C149.2@38.215,16.994 ; 39.538,16.975 U47.4@39.942,16.977 39.941,16.548 ; 40.891,16.33 U47.5@40.892,16.977
NetC151_2: C151.2 R292.2 SB48.1 TP8.1 U48.4 | length 7
  Top Layer w0.508: 28.872,15.283 TP8.1@29.55,15.284 ; 28.926,16.84 C151.2@29.55,16.84 ; 29.55,14.605 TP8.1@29.55,15.284 ; 29.55,15.961 TP8.1@29.55,15.284 ; 29.55,16.34 C151.2@29.55,16.84 ; 30.173,16.84 C151.2@29.55,16.84 ; 30.229,15.283 TP8.1@29.55,15.284 ; 30.579,16.939 30.597,16.921 U48.4@31.115,16.921 ; 30.617,15.499 R292.2@31.116,15.5 31.216,15.6 U48.4@31.216,16.924
NetC154_1: C154.1 U42.5 | length 9.1
  Top Layer w0.127: U42.5@53.123,19.585 53.124,19.583 53.124,18.905 54.074,17.955 54.074,14.526 54.455,14.145 55.979,14.145 56.36,14.526 C154.1@56.36,15.604
NetC154_2: C154.2 U42.7 | length 2.9
  Top Layer w0.127: U42.7@55.663,19.585 55.664,19.583 55.664,18.651 56.36,17.955 C154.2@56.36,17.005
NetC155_1: C155.1 U42.8 | length 2.9
  Top Layer w0.127: U42.8@56.933,19.585 56.934,19.583 56.934,18.27 57.63,17.574 C155.1@57.63,17.005
NetC169_2: C169.2 L8.1 SB84.2 SB85.2 SB86.1 | length 7.2
  Bottom Layer w0.508: C169.2@74.521,126.609 74.521,127.389 75.454,128.324 75.454,129.558 75.482,129.586 75.743,129.842 78.93,129.842 79.096,129.68 SB84.2@79.093,129.68
NetC171_2: C171.2 R310.2 SB116.2 | length 9.2
  Bottom Layer w0.254: C171.2@74.966,123.746 74.966,122.225 74.963,122.222 75.018,122.167 75.283,121.905 SB116.2@75.283,114.696
NetC177_2: C177.2 R313.1 X2.3 | length 2.4
  Bottom Layer w0.127: X2.3@68.134,119.499 68.133,119.499 68.102,119.53 68.102,120.896 69.073,120.896 C177.2@69.103,120.866
NetC178_2: C178.2 R317.1 X2.1 | length 8.6
  Bottom Layer w0.127: R317.1@65.953,120.866 R317.1@65.953,120.866 ; R317.1@65.954,120.866 65.954,120.338 66.703,119.588 66.703,117.849 67.028,117.523 69.187,117.523 69.482,117.818 69.482,118.448 70.858,118.448 70.878,118.428 C178.2@71.002,118.299
NetC181_1: C181.1 R311.2 R316.1 SB102.2 U53.4 | length 6.5
  Bottom Layer w0.254: R316.1@111.036,121.206 111.354,120.889 112.367,120.889 112.413,120.841 U53.4@114.14,120.841 ; SB102.2@113.604,119.428 113.67,119.497 C181.1@114.907,119.497 114.907,120.444 114.511,120.841 U53.4@114.14,120.841 ; U53.4@114.141,120.843 U53.4@114.14,120.841
NetC181_2: C181.2 Q4.1 R318.1 U53.3 | length 6.4
  Bottom Layer w0.254: Q4.1@114.333,115.534 114.336,115.534 114.907,116.106 C181.2@114.907,118.597 115.09,118.595 116.114,119.619 116.304,119.619 116.336,119.653 116.34,119.657 U53.3@116.341,120.843
NetC182_2: C182.2 R314.1 X3.1 | length 3.8
  Bottom Layer w0.127: R314.1@63.906,120.896 63.906,120.625 63.901,120.62 63.901,118.491 64.651,117.742 X3.1@64.651,117.376
NetC183_2: C183.2 R315.1 X3.2 | length 3.8
  Bottom Layer w0.127: X3.2@62.149,117.376 62.149,117.724 62.903,118.478 R315.1@62.903,120.896
NetCN1_4: CN1.4 R1.1 | length 3
  Top Layer w0.127: R1.1@14.192,166.377 14.244,166.428 CN1.4@17.135,166.429
NetCN1_8: CN1.8 SB1.1 | length 3
  Top Layer w0.127: SB1.1@14.192,161.372 14.214,161.348 CN1.8@17.135,161.349
NetCN2_14: CN2.14 R3.1 | length 5
  Top Layer w0.127: CN2.14@76.2,163.195 76.97,162.423 76.97,159.408 76.683,159.118 76.683,158.608 R3.1@76.68,158.608
NetCN2_15: CN2.15 R2.2 | length 7.8
  Top Layer w0.127: CN2.15@73.66,165.735 74.775,164.617 74.775,161.719 75.283,161.211 R2.2@75.283,158.608
NetCN2_17: CN2.17 R4.2 | length 7.8
  Top Layer w0.127: CN2.17@71.12,165.735 72.362,164.49 72.362,162.354 72.725,161.991 R4.2@72.726,158.624
NetCN2_19: CN2.19 R6.2 | length 7.8
  Top Layer w0.127: CN2.19@68.58,165.735 69.949,164.363 69.949,162.227 70.203,161.973 R6.2@70.203,158.608
NetCN2_24: CN2.24 R5.1 | length 4.7
  Top Layer w0.127: CN2.24@63.5,163.195 63.635,163.06 R5.1@63.635,158.587
NetCN2_26: CN2.26 R7.1 | length 4.9
  Top Layer w0.127: CN2.26@60.96,163.195 61.059,163.093 R7.1@61.059,158.356
NetCN2_27: CN2.27 R8.2 | length 7.9
  Top Layer w0.127: CN2.27@58.42,165.735 59.604,164.551 59.604,158.422 R8.2@59.535,158.354
NetCN2_29: CN2.29 R11.2 | length 8.2
  Top Layer w0.127: CN2.29@55.88,165.735 57.122,164.49 57.122,161.694 57.884,160.932 R11.2@57.884,158.354
NetCN2_30: CN2.30 R10.1 | length 5
  Top Layer w0.127: CN2.30@55.88,163.195 56.36,162.715 R10.1@56.36,158.354
NetCN2_32: CN2.32 R12.1 | length 5.4
  Top Layer w0.127: R12.1@51.915,158.356 51.915,161.768 CN2.32@53.34,163.195
NetCN3_1: CN3.1 R19.2 R302.1 R303.2 U2.1 | length 19.4
  Top Layer w0.254: U2.1@113.861,160.655 113.883,160.63 113.883,152.265 R19.2@114.084,152.068 ; R19.2@114.084,152.067 115.161,152.067 v1(115.542,151.684)
  Bottom Layer w0.254: R303.2@108.684,150.736 108.684,151.305 109.753,152.375 114.851,152.375 v1(115.542,151.684) R302.1@115.542,150.738 R302.1@115.542,150.734
NetCN4_2: CN4.2 CN4.4 CN4.6 CN4.8 CN4.10 CN4.12 R18.1 | length 19.2
  Top Layer w0.254: CN4.12@5.715,136.525 CN4.10@5.715,139.065 CN4.8@5.715,141.605 CN4.6@5.715,144.145 CN4.4@5.715,146.685
  Top Layer w0.305: CN4.2@5.715,149.225 5.715,150.825 7.338,152.448 R18.1@9.939,152.448
  Bottom Layer w0.254: CN4.4@5.715,146.685 CN4.2@5.715,149.225
NetCN4_14: CN4.14 R77.1 | length 4.3
  Top Layer w0.127: CN4.14@5.715,133.985 5.834,133.866 R77.1@9.96,133.866
NetCN4_15: CN4.15 R86.2 | length 7.3
  Top Layer w0.127: CN4.15@3.175,131.445 4.318,130.302 R86.2@9.96,130.302
NetCN4_17: CN4.17 R92.2 | length 7.4
  Top Layer w0.127: CN4.17@3.175,128.905 4.394,127.683 9.754,127.683 R92.2@9.96,127.889
NetCN4_19: CN4.19 R100.2 | length 7.3
  Top Layer w0.127: CN4.19@3.175,126.365 4.394,125.143 9.919,125.143 R100.2@9.96,125.103
NetCN4_24: CN4.24 R113.1 | length 4.3
  Top Layer w0.127: CN4.24@5.715,121.285 5.842,121.158 R113.1@9.96,121.158
NetCN4_26: CN4.26 R120.1 | length 4.3
  Top Layer w0.127: CN4.26@5.715,118.745 5.857,118.603 R120.1@9.96,118.603
NetCN4_27: CN4.27 R126.2 | length 7.7
  Top Layer w0.127: CN4.27@3.175,116.205 4.394,114.983 7.084,114.983 8.052,115.951 R126.2@9.96,115.951
NetCN4_29: CN4.29 R151.2 | length 7.7
  Top Layer w0.127: CN4.29@3.175,113.665 4.394,112.443 7.592,112.443 8.557,113.408 R151.2@9.96,113.41
NetCN4_30: CN4.30 R128.1 | length 4.7
  Top Layer w0.127: CN4.30@5.715,113.665 7.417,113.665 8.433,114.681 R128.1@9.96,114.681
NetCN4_32: CN4.32 R155.1 | length 4.3
  Top Layer w0.127: CN4.32@5.715,111.125 5.842,111.252 R155.1@9.96,111.252
NetCN7_1: CN7.1 R310.1 SB75.2 U5.1 | length 82.4
  Top Layer w0.254: v1(81.379,112.888) 81.722,112.545 83.436,112.545 84.046,111.935 84.046,109.776 85.253,108.57 102.144,108.57 105.001,111.427 108.176,111.427 109.192,112.443 109.192,135.176 110.299,136.284 v1(111.351,136.284) ; U5.1@113.883,145.288 113.881,141.285 CN7.1@113.884,141.285
  L4_SIG w0.254: v1(78.712,122.222) 78.712,120.571 81.633,117.65 81.633,113.713 81.379,113.459 v1(81.379,112.888)
  Bottom Layer w0.254: R310.1@76.363,122.222 v1(78.712,122.222) ; v1(111.351,136.284) 113.891,136.284 113.891,136.665 113.883,136.672 CN7.1@113.884,141.285
NetCN8_1: CN8.1 R152.1 SB16.2 U7.1 | length 62.3
  Top Layer w0.254: R152.1@78.461,110.73 78.461,110.028 80.605,107.883 103.286,107.883 105.969,110.566 109.474,110.566 110.462,111.554 110.462,115.364 109.7,116.126 109.7,124.381 110.03,124.711 113.688,124.711 113.815,124.838 113.815,129.459 CN8.1@113.831,129.474 113.83,134.516 SB16.2@113.891,134.577
NetCN9_1: CN9.1 R154.2 U9.1 | length 5
  Top Layer w0.406: R154.2@87.648,112.042 89.052,112.042
  Top Layer w0.508: CN9.1@86.876,115.278 87.648,114.508 87.648,112.042 R154.2@87.647,112.042
NetCN11_2: CN11.2 U17.6 | length 8.5
  Top Layer w0.127: CN11.2@10.414,87.603 13.383,87.602 15.222,85.763 U17.6@18.14,85.763
NetCN11_3: CN11.3 U17.10 | length 8.4
  Top Layer w0.127: CN11.3@10.414,84.833 10.414,84.833 14.501,84.833 16.172,83.162 U17.10@18.14,83.163
NetCN11_6: CN11.6 U17.5 | length 11.3
  Top Layer w0.127: CN11.6@7.874,88.988 12.761,88.986 15.337,86.411 U17.5@18.14,86.413
NetCN11_8: CN11.8 U17.7 | length 12.4
  Top Layer w0.127: CN11.8@7.874,83.448 CN11.8@7.874,83.448 7.874,84.15 10.132,86.408 13.688,86.408 14.983,85.113 U17.7@18.14,85.113
NetCN11_9: CN11.9 SB38.2 SB39.1 U22.7 | length 16.5
  Top Layer w0.127: CN11.9@7.874,80.678 10.909,80.678 14.196,77.391 14.196,75.994 15.829,74.361 SB38.2@17.044,74.362 17.137,74.455 SB39.1@18.501,74.457 18.636,74.32 U22.7@18.637,72.141
NetCN14_11: CN14.11 R200.1 R203.2 | length 5.2
  Top Layer w0.127: R200.1@106.975,74.724 106.975,73.688 R203.2@107.003,73.66 CN14.11@111.125,73.66
NetCN14_17: CN14.17 R212.2 | length 4.2
  Top Layer w0.127: R212.2@106.991,66.294 110.871,66.294 CN14.17@111.125,66.04
NetCN14_19: CN14.19 R214.2 | length 4.1
  Top Layer w0.127: R214.2@107.003,63.5 CN14.19@111.125,63.5
NetCN20_1: CN20.1 R216.2 R219.1 | length 4.7
  Top Layer w0.127: R219.1@95.711,59.639 R216.2@95.71,60.957 ; R216.2@95.711,60.96 R216.2@95.71,60.957 ; CN20.1@99.06,60.96 99.06,60.957 R216.2@95.71,60.957
NetCN20_3: CN20.3 R220.2 | length 3.4
  Top Layer w0.127: R220.2@95.711,58.318 95.71,58.316 95.711,58.318 95.811,58.42 CN20.3@99.06,58.42
NetCN20_7: CN20.7 R231.2 | length 3.6
  Top Layer w0.127: R231.2@95.798,52.426 R231.2@95.798,52.426 98.146,52.426 CN20.7@99.06,53.34
NetCN20_8: CN20.8 Q1.3 R226.2 | length 9.5
  Top Layer w0.127: Q1.3@96.223,55.88 95.573,55.23 R226.2@95.573,53.619 97.003,53.619 97.965,54.582 100.355,54.582 CN20.8@101.6,53.34
NetCN31_C1: CN31.C1 D10.8 | length 4
  Top Layer w0.127: v1(62.014,33.884) 62.233,33.884 63.492,32.624 D10.8@63.494,32.233
  Bottom Layer w0.127: CN31.C1@60.801,32.965 61.719,33.884 v1(62.014,33.884)
NetCN31_C2: CN31.C2 D10.7 | length 9.9
  Top Layer w0.127: v1(61.742,36.322) 63.894,34.171 D10.7@63.894,32.233
  Bottom Layer w0.127: CN31.C2@58.261,32.965 61.618,36.322 v1(61.742,36.322)
NetCN31_C3: CN31.C3 D10.6 | length 13.7
  Top Layer w0.127: v1(62.967,36.373) 62.967,35.865 62.964,35.862 64.292,34.534 D10.6@64.294,32.233
  Bottom Layer w0.127: CN31.C3@55.721,32.965 59.558,36.802 62.537,36.802 v1(62.967,36.373)
NetCN31_C4: CN31.C4 U42.13 | length 29.2
  Top Layer w0.127: v1(62.202,21.384) 63.284,20.302 63.284,19.583 U42.13@63.283,19.585
  Bottom Layer w0.127: CN31.C4@53.181,32.965 51.149,30.933 51.149,26.332 50.01,25.193 50.01,20.622 50.899,19.733 60.551,19.733 v1(62.202,21.384)
NetCN31_C7: CN31.C7 D10.5 | length 31.8
  Top Layer w0.127: D10.5@64.694,32.233 64.757,32.296 v1(66.726,32.296)
  Bottom Layer w0.127: CN31.C7@55.721,8.365 56.855,9.5 58.953,9.5 62.456,13.002 62.456,17.193 66.639,21.377 66.639,32.21 v1(66.726,32.296)
NetCN31_C8: CN31.C8 U42.12 | length 17.2
  Top Layer w0.127: U42.12@62.013,19.585 62.014,19.583 62.014,18.016 v1(62.075,17.955)
  Bottom Layer w0.127: CN31.C8@53.181,8.365 54.784,9.968 58.66,9.968 62.075,13.383 v1(62.075,17.955)
NetCN31_S2: CN31.S2 R290.1 U42.9 U44.1 | length 29.1
  Top Layer w0.127: U44.1@43.043,23.8 43.043,24.272 43.457,24.686 v1(45.025,24.686) ; U42.9@58.203,19.585 58.204,19.583 58.204,18.397 58.9,17.701 58.9,17.005 v1(59.916,17.005)
  Bottom Layer w0.127: CN31.S2@45.561,26.165 45.561,25.222 v1(45.025,24.686) 45.025,19.904 47.924,17.005 v1(59.916,17.005)
NetCN32_2: CN32.2 SW2.6 SW2.9 SW4.5 | length 72.5
  Top Layer w0.127: SW2.6@68.446,150.262 SW2.9@68.446,152.762
  L4_SIG w0.102: SW2.9@68.446,152.762 70.018,152.761 75.41,147.368 79.982,147.368 80.871,146.479 80.871,143.304 82.014,142.161 82.014,127.302 82.776,126.54 82.776,120.825 83.986,119.615 85.249,119.615 85.585,119.951 87.994,119.951 CN32.2@89.332,118.613
  Bottom Layer w0.127: SW4.5@48.889,153.192 50.013,152.067 56.766,152.067 57.528,151.305 67.401,151.305 SW2.6@68.446,150.262
NetD1_1: D1.1 L2.1 T1.1 T1.2 T1.5 T1.6 T1.8 | length 5.8
  Top Layer w0.254: T1.8@45.062,99.396 45.362,99.096 46.234,99.096 46.438,99.3
  Top Layer w0.508: 42.438,98.374 L2.1@42.438,100.554 ; 44.028,101.709 D1.1@46.027,101.709
NetD2_1: D2.1 U17.20 | length 80.1
  Top Layer w0.127: U17.20@25.04,83.813 27.221,83.812 29.055,85.646 29.055,90.091 30.96,91.996 40.256,91.996 43.05,94.79 v1(44.219,94.79) ; D2.1@84.401,81.149 85.039,81.148 v1(85.367,80.82)
  L4_SIG w0.102: v1(44.219,94.79) 45.209,94.79 46.683,96.263 52.093,96.263 53.49,94.866 55.725,94.866 56.106,95.247 57.046,95.247 58.544,93.749 62.989,93.749 65.961,90.777 65.961,84.427 68.374,82.014 76.911,82.014 77.541,82.644 83.543,82.644 v1(85.367,80.82)
NetD2_2: D2.2 JP8.1 | length 3.1
  Top Layer w0.127: D2.2@84.401,83.289 87.518,83.289 JP8.1@87.538,83.27
NetD10_2: D10.2 U42.16 | length 2.2
  Top Layer w0.127: U42.16@63.283,28.765 63.284,28.763 63.284,29.451 63.894,30.061 D10.2@63.894,30.733
NetD10_3: D10.3 U42.15 | length 2.1
  Top Layer w0.127: D10.3@64.294,30.733 64.292,29.022 U42.15@64.553,28.765 64.554,28.763 U42.15@64.553,28.765
NetD10_4: D10.4 U42.11 | length 14.8
  Top Layer w0.127: U42.11@60.743,19.585 60.744,19.583 60.744,25.258 62.332,26.845 64.742,26.845 65.377,27.48 65.377,29.893 64.694,30.577 D10.4@64.694,30.733
NetD11_2: D11.2 JP18.1 | length 66.2
  Top Layer w0.127: v5(75.798,17.777) 75.798,13.858 77.213,12.443 D11.2@77.213,10.363
  L4_SIG w0.102: JP18.1@62.078,68.402 JP18.1@62.078,67.615 62.078,63.083 67.457,57.703 67.457,52.755 66.98,52.278 66.98,45.313 69.314,42.979 69.314,21.742 73.279,17.777 v5(75.798,17.777)
NetJP2_1: JP2.1 R165.2 | length 3.7
  Top Layer w0.127: R165.2@23.521,102.027 25.766,102.027 JP2.1@26.782,103.044
NetJP4_1: JP4.1 R181.2 | length 3.7
  Top Layer w0.508: R181.2@23.52,92.788 25.715,92.786 JP4.1@26.782,93.854
NetJP5_1: JP5.1 RV2.2 U14.1 | length 12
  Top Layer w0.127: JP5.1@103.701,100.167 105.208,100.167 105.915,99.46 U14.1@106.934,99.46 ; U14.1@106.934,99.46 114.668,99.459 RV2.2@115.189,99.98
NetJP5_2: JP5.2 R164.2 | length 11.9
  Top Layer w0.127: JP5.2@103.701,97.627 102.091,97.627 101.244,98.473 101.244,101.298 102.547,102.6 R164.2@106.934,102.6
NetJP5_3: JP5.3 R174.1 R179.1 | length 9.1
  Top Layer w0.127: R174.1@98.762,93.377 100.472,95.087 JP5.3@103.701,95.087 105.079,95.087 105.664,94.502 R179.1@106.934,94.502
NetJP6_2: JP6.2 L9.1 SB90.1 | length 49.8
  Top Layer w0.508: v1(75.791,111.681) 73.124,109.014 73.124,103.553 73.759,102.918 73.759,100.505 72.743,99.489 72.743,95.933 75.156,93.52 77.569,93.52 78.204,92.885 78.204,90.599 80.427,88.377 JP6.2@80.772,88.377
  L4_SIG w0.508: v1(75.791,111.681) 75.664,111.808 75.664,113.955 74.902,114.717 74.902,122.476 77.404,124.978 v1(80.02,124.978)
  Bottom Layer w0.508: SB90.1@77.696,125.278 77.823,125.278 78.123,124.978 v1(80.02,124.978)
NetJP7_2: JP7.2 U6.6 | length 42.8
  Top Layer w0.127: U6.6@62.503,121.346 62.502,119.855 62.484,119.837 62.484,119.791 61.112,118.42 61.112,116.586 61.702,115.999 63.18,115.999 v1(63.421,115.758)
  Bottom Layer w0.127: v1(63.421,115.758) 63.472,115.809 64.12,115.809 64.412,115.517 64.412,114.932 63.777,114.297 63.777,108.506 66.012,106.271 69.339,106.271 71.422,104.188 71.422,94.79 72.489,93.723 72.489,89.83 JP7.2@70.924,88.265
NetJP9_1: JP9.1 U17.17 | length 11.4
  Top Layer w0.127: U17.17@25.04,81.863 26.617,81.862 27.15,81.328 27.15,79.55 28.191,78.509 JP9.1@33.995,78.51
NetJP9_3: JP9.3 U22.1 | length 32.2
  Top Layer w0.127: U22.1@17.367,67.391 v1(17.366,69.771)
  L4_SIG w0.102: v1(17.366,69.771) 19.022,71.427 19.022,82.09 20.546,83.614 27.277,83.614 28.547,84.884 28.547,84.91 28.649,85.011 32.573,85.011 JP9.3@33.995,83.59
NetJP16_1: JP16.1 U35.A2 | length 36
  Top Layer w0.127: v1(86.535,47.572) 86.561,47.546 86.561,47.445 86.576,47.429 U35.A2@86.577,46.966
  Bottom Layer w0.127: v1(86.535,47.572) 86.942,47.165 87.627,47.165 88.11,46.683 88.11,44.625 87.856,44.371 87.856,43.558 88.293,43.122 88.293,40.836 90.988,38.14 103.116,38.14 104.216,37.04 104.216,33.901 104.921,33.195 108.862,33.195 JP16.1@110.084,34.417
